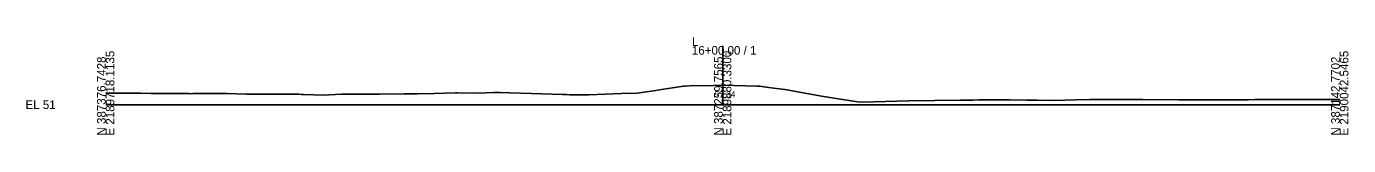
# Model space of a CAD drawing. Extents: x -26 to 2190750, y -10 to 388496.
# Drawn here: x -25.7 to 402.8, y -9.7 to 21.8 of the extents above; entities that cross this region are included whole.
import ezdxf

# ---------------------------------------------------------------- set-up
doc = ezdxf.new("R2010")
doc.units = 0
for name, color, linetype in [('Default', 7, 'Continuous'), ('Exist Cross Section Cell', 7, 'Continuous'), ('Exist XS Center Line Elevation Label', 7, 'Continuous'), ('Exist XS Ground Line', 7, 'Continuous')]:
    doc.layers.add(name, color=color, linetype=linetype)

msp = doc.modelspace()

# ---------------------------------------------------------------- linework, layer by layer
at = {"layer": 'Exist Cross Section Cell'}
for p, q in [((200, 0), (200, 19.02)), ((0, 0), (200, 0)), ((200, 0), (400, 0))]:
    msp.add_line(p, q, dxfattribs=at)
at = {"layer": 'Exist XS Ground Line'}
msp.add_lwpolyline([(0, 3.74), (2.43, 3.76), (11.29, 3.72), (14.76, 3.65), (20.47, 3.67), (27.09, 3.59), (27.63, 3.57), (28.39, 3.58), (39.42, 3.58), (45.48, 3.43), (51.75, 3.43), (62.58, 3.37), (63.45, 3.34), (64.08, 3.31), (70.61, 3.14), (76.41, 3.37), (77.78, 3.39), (79.68, 3.41), (88.74, 3.44), (96.78, 3.48), (101.07, 3.56), (106.43, 3.65), (113.4, 3.84), (113.87, 3.84), (120.76, 3.77), (125.73, 3.92), (127.93, 3.94), (130.97, 3.86), (138.06, 3.61), (148.07, 3.32), (149.42, 3.27), (150.39, 3.25), (156.58, 3.22), (167.23, 3.59), (172.22, 3.71), (178.35, 4.62), (179.55, 4.8), (182.32, 5.22), (187.3, 5.98), (187.82, 6.01), (189.09, 6.07), (196.96, 6.26), (200.04, 6.34), (203.69, 6.24), (211.07, 6.04), (212.07, 5.98), (212.62, 5.95), (215.65, 5.51), (220.14, 4.9), (227.93, 3.49), (232.02, 2.73), (238.81, 1.66), (244.39, 0.8), (248.97, 0.93), (260.28, 1.3), (277.1, 1.48), (281.01, 1.52), (282.99, 1.54), (292.8, 1.63), (298.55, 1.48), (301.92, 1.44), (307.12, 1.4), (310.88, 1.51), (314.29, 1.58), (319.02, 1.64), (323.21, 1.67), (334.05, 1.66), (335.54, 1.65), (336.12, 1.65), (347.87, 1.57), (350.11, 1.59), (353.21, 1.57), (357.27, 1.58), (360.2, 1.58), (364.44, 1.61), (370.31, 1.63), (372.53, 1.64), (378.27, 1.64), (384.86, 1.65), (387.41, 1.68), (397.19, 1.69), (400, 1.66)], dxfattribs=at)

# ---------------------------------------------------------------- texts
at = {"layer": 'Default'}
msp.add_text('-', height=0.0001, dxfattribs=at).set_placement((0, 0))
at = {"layer": 'Exist Cross Section Cell'}
for s, p in [('L', (190, 19.02)), ('16+00.00 / 1', (190, 16.22)), ('EL 51', (-26, -1.4))]:
    msp.add_text(s, height=2.8, dxfattribs=at).set_placement(p)
for s, p in [('E 2189718.1135', (2.8, -10)), ('E 2189880.3300', (202.8, -10)), ('E 2190042.5465', (402.8, -10)), ('N 387376.7428', (0, -10)), ('N 387259.7565', (200, -10)), ('N 387142.7702', (400, -10))]:
    msp.add_text(s, height=2.8, rotation=90, dxfattribs=at).set_placement(p)
at = {"layer": 'Exist XS Center Line Elevation Label'}
msp.add_text('57.34', height=2, dxfattribs=at).set_placement((197.38, 2.34))

doc.saveas('drawing.dxf')
